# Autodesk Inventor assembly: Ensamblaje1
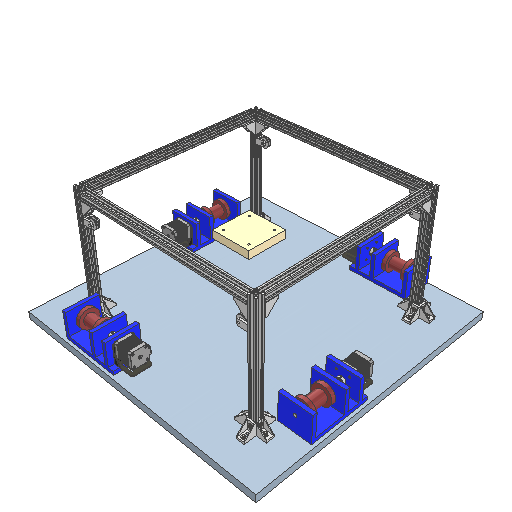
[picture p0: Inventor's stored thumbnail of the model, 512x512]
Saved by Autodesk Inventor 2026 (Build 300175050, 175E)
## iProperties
Created: 2025-06
Part Number: Ensamblaje1
Document SubType Name: Assembly
Designer: piero
Author: piero
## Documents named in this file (9)
- C:\Users\piero\OneDrive\Documentos\UTEC\Ciclo 2025-1\PFC_1\ModeloBase\Ensamblaje1.iam
- C:\Users\piero\OneDrive\Documentos\UTEC\Ciclo 2025-1\PFC_1\ModeloBase\Mesa.ipt
- C:\Users\piero\OneDrive\Documentos\UTEC\Ciclo 2025-1\PFC_1\ModeloBase\V-slot.ipt
- C:\Users\piero\OneDrive\Documentos\UTEC\Ciclo 2025-1\PFC_1\ModeloBase\Ensamblaje2.iam
- C:\Users\piero\OneDrive\Documentos\UTEC\Ciclo 2025-1\PFC_1\ModeloBase\Plataforma.ipt
- C:\Users\piero\OneDrive\Documentos\UTEC\Ciclo 2025-1\PFC_1\ModeloBase\Esquinero.ipt
- C:\Users\piero\OneDrive\Documentos\UTEC\Ciclo 2025-1\PFC_1\ModeloBase\polea.ipt
- C:\Users\piero\OneDrive\Documentos\UTEC\Ciclo 2025-1\PFC_1\ModeloBase\V-slot_2.ipt
- C:\Users\piero\OneDrive\Documentos\Inventor\Content Center Files\R2026\es-ES\BS EN ISO 7046-2 H\BS EN ISO 7046-2 H - M5x6 - 8.8 - H1.ipt
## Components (50 placed, 8 different names)
1. Mesa:1 — Coincidencia:1, Coincidencia:2, Coincidencia:3, Coincidencia:4
2. V-slot:1 — Coincidencia:1
3. V-slot:2 — Coincidencia:4
4. V-slot:3 — Coincidencia:3
5. V-slot:4 — Coincidencia:2
6. Ensamblaje2:1 [sub-assembly]
7. Ensamblaje2:2 [sub-assembly]
8. Ensamblaje2:5 [sub-assembly]
9. Ensamblaje2:7 [sub-assembly]
10. Plataforma:1
11. V-slot_2:1
12. V-slot_2:2
13. V-slot_2:3
14. V-slot_2:4
15. Esquinero:5
16. Esquinero:6
17. Esquinero:7
18. Esquinero:8
19. Esquinero:9
20. Esquinero:10
21. Esquinero:11
22. Esquinero:12
23. Esquinero:13
24. Esquinero:14
25. Esquinero:15
26. Esquinero:16
27. Esquinero:17
28. Esquinero:18
29. Esquinero:19
30. Esquinero:20
31. Esquinero:21
32. Esquinero:22
33. Esquinero:23
34. Esquinero:24
35. Esquinero:25
36. Esquinero:26
37. Esquinero:27
38. Esquinero:28
39. BS EN ISO 7046-2 H M5x6 - 8.8 - H1:1
40. BS EN ISO 7046-2 H M5x6 - 8.8 - H1:2
41. BS EN ISO 7046-2 H M5x6 - 8.8 - H1:3
42. BS EN ISO 7046-2 H M5x6 - 8.8 - H1:4
43. BS EN ISO 7046-2 H M5x6 - 8.8 - H1:5
44. BS EN ISO 7046-2 H M5x6 - 8.8 - H1:6
45. BS EN ISO 7046-2 H M5x6 - 8.8 - H1:7
46. BS EN ISO 7046-2 H M5x6 - 8.8 - H1:8
47. polea:5
48. polea:6
49. polea:7
50. polea:8
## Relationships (4: Mate 4)
- Coincidencia:1 [Mate]: Mesa:1 ↔ V-slot:1
- Coincidencia:2 [Mate]: Mesa:1 ↔ V-slot:4
- Coincidencia:3 [Mate]: Mesa:1 ↔ V-slot:3
- Coincidencia:4 [Mate]: Mesa:1 ↔ V-slot:2
